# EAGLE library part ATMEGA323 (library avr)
MICROCONTROLLER 32 Kbytes FLASH 2 Kbytes SRAM 1 Kbytes EEPROM USART 8-channel 10 bit ADC
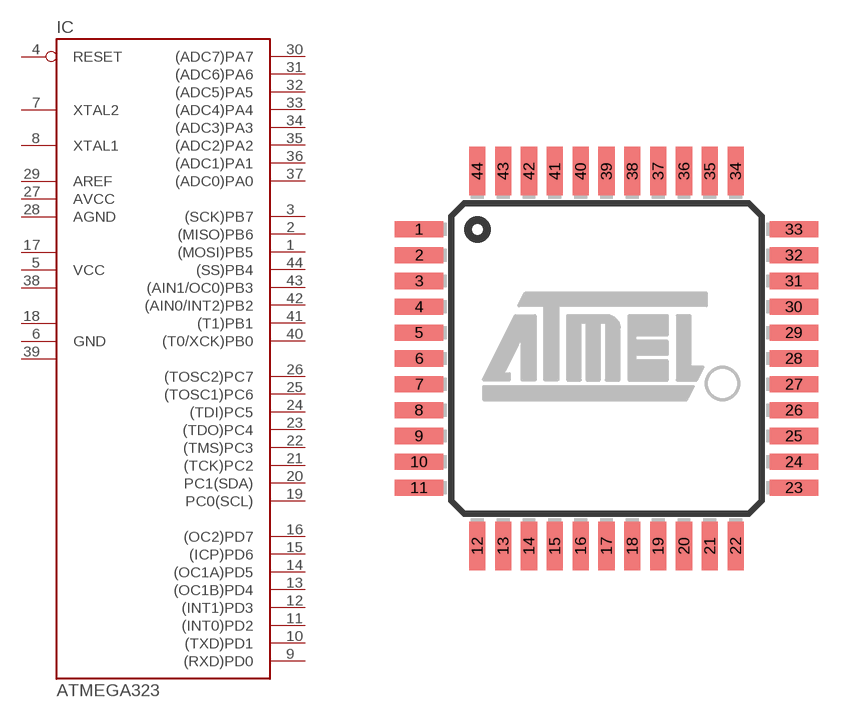
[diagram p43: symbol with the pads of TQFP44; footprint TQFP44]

Designator prefix IC

## ATMEGA323-8A, ATMEGA323L-4A  [TQFP44]
1  (MOSI)PB5
2  (MISO)PB6
3  (SCK)PB7
4  RESET  in
5  VCC  pwr
6  GND  pwr
7  XTAL2
8  XTAL1
9  (RXD)PD0
10  (TXD)PD1
11  (INT0)PD2
12  (INT1)PD3
13  (OC1B)PD4
14  (OC1A)PD5
15  (ICP)PD6
16  (OC2)PD7
17  VCC1  pwr
18  GND1  pwr
19  PC0(SCL)
20  PC1(SDA)
21  (TCK)PC2
22  (TMS)PC3
23  (TDO)PC4
24  (TDI)PC5
25  (TOSC1)PC6
26  (TOSC2)PC7
27  AVCC  pwr
28  AGND  pwr
29  AREF  pwr
30  (ADC7)PA7
31  (ADC6)PA6
32  (ADC5)PA5
33  (ADC4)PA4
34  (ADC3)PA3
35  (ADC2)PA2
36  (ADC1)PA1
37  (ADC0)PA0
38  VCC2  pwr
39  GND2  pwr
40  (T0/XCK)PB0
41  (T1)PB1
42  (AIN0/INT2)PB2
43  (AIN1/OC0)PB3
44  (SS)PB4

## Footprint TQFP44 (pad centres in mm)
Thin Plasic Quad Flat Package
smd 1.5 x 0.5: 1 -5.8,4; 2 -5.8,3.2; 3 -5.8,2.4; 4 -5.8,1.6; 5 -5.8,0.8; 6 -5.8,0; 7 -5.8,-0.8; 8 -5.8,-1.6; 9 -5.8,-2.4; 10 -5.8,-3.2; 11 -5.8,-4; 23 5.8,-4; 24 5.8,-3.2; 25 5.8,-2.4; 26 5.8,-1.6; 27 5.8,-0.8; 28 5.8,0; 29 5.8,0.8; 30 5.8,1.6; 31 5.8,2.4; 32 5.8,3.2; 33 5.8,4
smd 0.5 x 1.5: 12 -4,-5.8; 13 -3.2,-5.8; 14 -2.4,-5.8; 15 -1.6,-5.8; 16 -0.8,-5.8; 17 0,-5.8; 18 0.8,-5.8; 19 1.6,-5.8; 20 2.4,-5.8; 21 3.2,-5.8; 22 4,-5.8; 34 4,5.8; 35 3.2,5.8; 36 2.4,5.8; 37 1.6,5.8; 38 0.8,5.8; 39 0,5.8; 40 -0.8,5.8; 41 -1.6,5.8; 42 -2.4,5.8; 43 -3.2,5.8; 44 -4,5.8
